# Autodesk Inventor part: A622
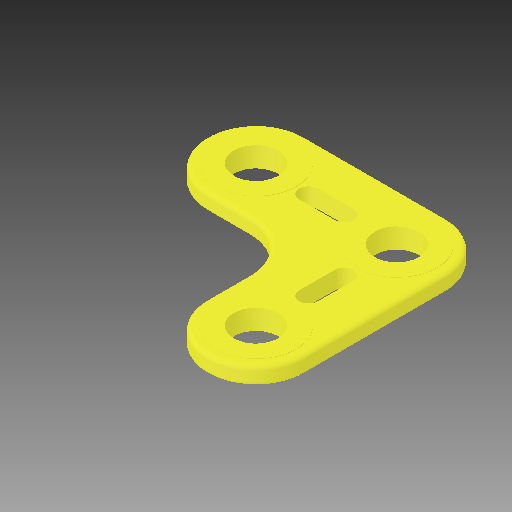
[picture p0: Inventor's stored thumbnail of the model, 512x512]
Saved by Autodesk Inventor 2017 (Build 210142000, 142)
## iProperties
Part Number: A622
Material: Générique
Document SubType Name: Modeling
Designer: ficho
Density: 1 g/cm^3
Appearance: Par défaut
Author: ficho
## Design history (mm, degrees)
feature "Solid1"
node "Solide1"
